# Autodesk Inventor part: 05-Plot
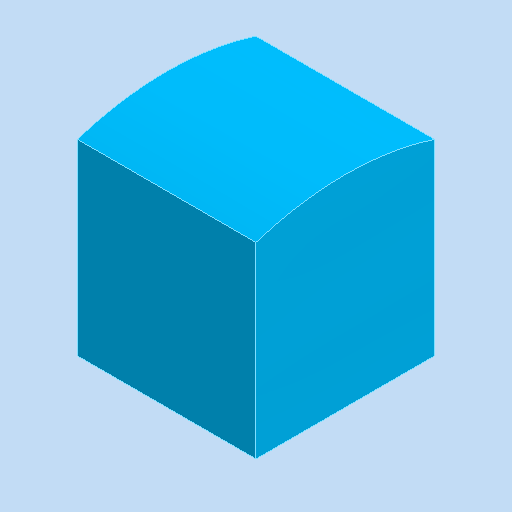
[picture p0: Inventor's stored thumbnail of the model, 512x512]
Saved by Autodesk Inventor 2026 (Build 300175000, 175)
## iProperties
Created: 2025-12
Part Number: 05-Plot
Material: Générique
Document SubType Name: Modeling
Designer: thierry.jost
Density: 1 g/cm^3
Appearance: Bleu ciel moyen
Author: thierry.jost
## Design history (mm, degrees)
sketch "Esquisse1"
  geometry: L1 (32.25, 15.5)-(-2.75, 15.5); L2 (-2.75, -15.5)-(32.25, -15.5); L3 (32.25, -15.5)-(32.25, 15.5); L4 (-2.75, 15.5)-(-2.75, -15.5); 1 further point
  constraints: 8 end point, 2 parallel, 1 horizontal, 1 perpendicular
  dimensions: "d0" = 31 distance of L2.end L1.start; "d1" = 15.5 distance from line of L1 point (0, 0); "d6" = 35 distance of L1.start L1.end
extrude "Extrusion1" new body sketch "Esquisse1" stored distance "d7" = 31; taper "d8" = 0 deg
sketch "Esquisse2"
  geometry: L1 (32.25, -15.5)-(32.25, 15.5) reference; C1 r 50 at (-17.75, 0); C2 r 56.322 at (-17.75, 0); 1 further point
  constraints: 2 centre point, 1 coincident, 1 tangent
  dimensions: "d9" = 100 diameter of C1
extrude "Extrusion2" cut sketch "Esquisse2" extent not by distance; stored distance "d10" = 0; taper "d11" = 0 deg
sketch "Esquisse4"
  geometry: C1 r 5.5 at (15.5, 15.5); 1 further point
  constraints: 1 centre point, 1 coincident
  dimensions: "d21" = 11 diameter of C1
extrude "Extrusion3" join sketch "Esquisse4" distance "d22" = 5; taper "d23" = 0 deg
sketch "Esquisse5"
  geometry: C1 r 5.5 at (0, 0) reference; 2 further points
  dimensions: "d34" = 0 distance of C1.centre point (0, 0); "d35" = 0 distance of C1.centre point (0, 0)
hole "Perçage2" sketch "Esquisse5" at (0, 0) diameter "d24" = 8.376; stored, may be unused: countersink angle "d28" = 90 deg, drill point angle "d30" = 118 deg; dims "d25" = 20, "d26" = 4, "d27" = 2, "d29" = 25
chamfer "Chanfrein1" distance "d31" = 1; stored, may be unused: second distance "d32" = 2, angle "d33" = 45 deg
node "Solide1"
